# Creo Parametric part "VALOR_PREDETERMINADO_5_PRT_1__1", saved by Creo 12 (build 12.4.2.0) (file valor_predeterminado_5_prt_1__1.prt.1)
Units: Custom; MM, KILOGRAM, SECS

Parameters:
  PTC_WM_ITERATION = "0"
  PTC_WM_VERSION = "-.0"
  PTC_WM_LIFECYCLE_STATE = "In Work"
  PTC_WM_LIFECYCLE = "MO_CADDocument"
  PTC_WM_CREATED_BY = "Maximilian Roepper (Z0017RMS: MO)"
  PTC_WM_CREATED_ON = "18-Sep-26 11:36:42 AM"
  PTC_WM_MODIFIED_BY = "Maximilian Roepper (Z0017RMS: MO)"
  PTC_WM_MODIFIED_ON = "18-Sep-26 11:36:46 AM"
  PDMLINKNUMBER = "PDM000071454873"
  PTC_WM_NAME = "valor_predeterminado_5_prt_1__1.prt"
  PTC_WM_NUMBER = "PDM000071454873"

Other parameters: WEIGHT, WEIGHT_FACTOR, WEIGHT_ADD, _MASS_TEMP, _DIFF_TEMP, MC_ERRORS, SUPPLIER

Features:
  1. coordinate system
  2. datum plane "PRT_YZ"
  3. datum plane "PRT_XY"
  4. datum plane "PRT_XZ"
  5. coordinate system
  6. datum axis
  7. datum axis
  8. datum axis
  9. coordinate system
  10. imported feature
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
Other named items: PRT, SIEMENS_MO, DRW_VIEW_ORG, PRT_X, PRT_Y, PRT_Z, CS0, ROUGH_GROB

Layers: 00_STD_CSYS-KSYS, 01_STD_PLANES-EBENEN, 02_STD_AXES-ACHSEN, 03_STD_CSYS-KSYS, 24_IMPORT_FEAT-IMPORT_KE

Surfaces: 20 cylinder, 16 plane, 8 torus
